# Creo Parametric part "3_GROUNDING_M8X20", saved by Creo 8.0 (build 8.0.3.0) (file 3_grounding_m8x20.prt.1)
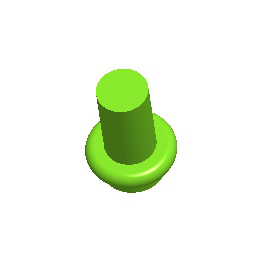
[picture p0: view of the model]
Units: millimeter Newton Second (mmNs); MM, TONNE, SECS

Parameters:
  PLACEMENT = "A"

Other parameters: THREADS_PER_INCH

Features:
  1. datum plane "RIGHT"
  2. datum plane "TOP"
  3. datum plane "FRONT"
  4. coordinate system
  5. protrusion

Layers: 0_ALL_AXIS, 0_ALL_CSYS, 0_ALL_CURVES, 0_ALL_PLANES, 0_ALL_POINTS, 0_ALL_SURFS, 2_GROUNDING_M8X20

Surfaces: 5 cylinder, 4 plane, 2 torus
